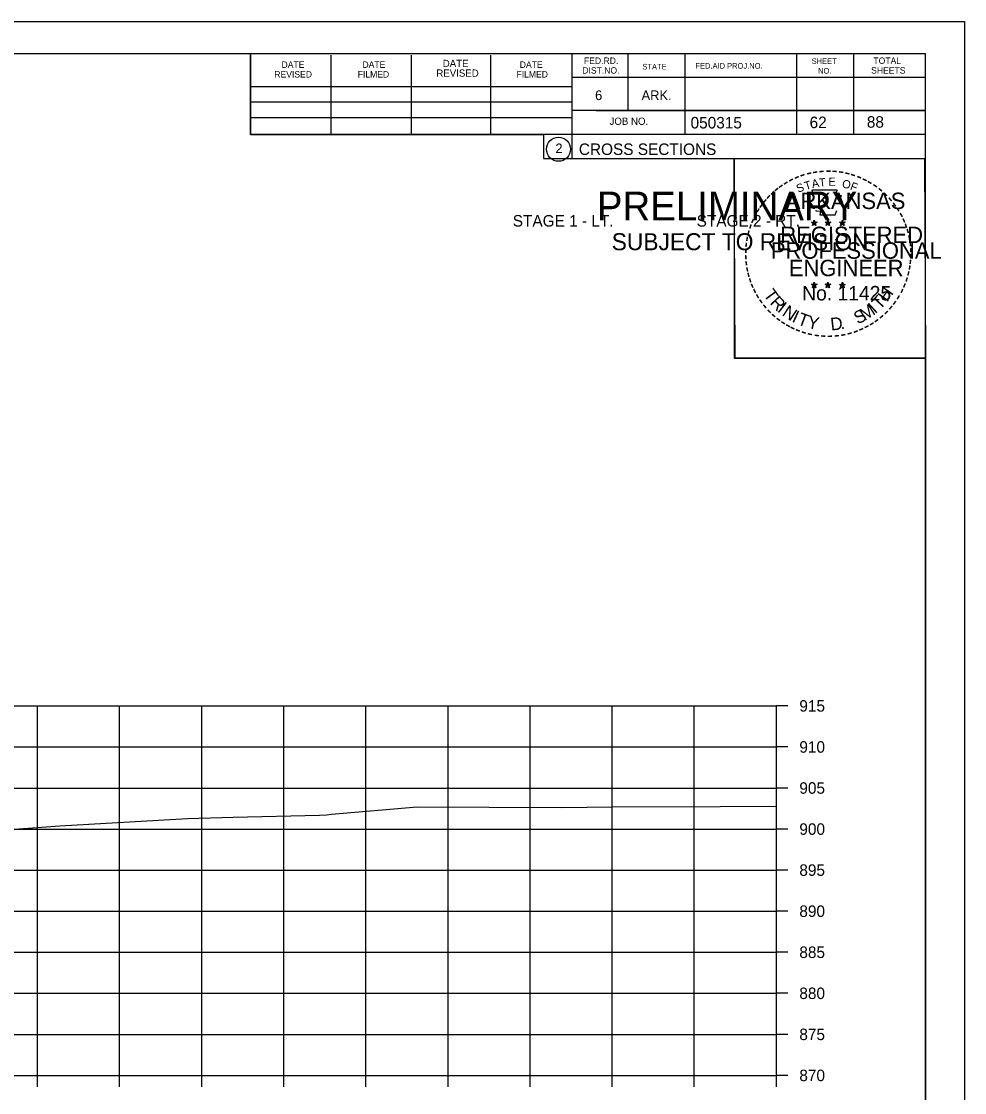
# Model space of a CAD drawing. Extents: x 1486524 to 1499135, y 326561 to 337924.
# Drawn here: x 1489030.9 to 1489145.8, y 330728.8 to 330859.3 of the extents above; entities that cross this region are included whole.
import ezdxf

# ---------------------------------------------------------------- set-up
doc = ezdxf.new("R2010")
doc.units = 0
for name, color, linetype in [('Default', 7, 'Continuous'), ('E_Const Align', 7, 'Continuous'), ('E_Const Align Station', 7, 'Continuous'), ('E_Ownership Information', 7, 'Continuous'), ('E_Property Line', 7, 'Continuous'), ('E_Quarter Calls', 7, 'Continuous'), ('E_Section Line', 7, 'Continuous'), ('E_Station Offset', 7, 'Continuous'), ('E_Tract Number', 7, 'Continuous'), ('S_SIXTEEN_SECTION', 7, 'Continuous')]:
    doc.layers.add(name, color=color, linetype=linetype)

msp = doc.modelspace()

# ---------------------------------------------------------------- linework, layer by layer
at = {"layer": 'E_Const Align'}
for p, q in [((1489122.89, 330730.91), (1489122.89, 330775.91)), ((1489124.29, 330775.91), (1489122.89, 330775.91)), ((1489124.29, 330770.91), (1489122.89, 330770.91)), ((1489124.29, 330765.91), (1489122.89, 330765.91)), ((1489124.29, 330760.91), (1489122.89, 330760.91)), ((1489124.29, 330755.91), (1489122.89, 330755.91)), ((1489124.29, 330750.91), (1489122.89, 330750.91)), ((1489124.29, 330745.91), (1489122.89, 330745.91)), ((1489124.29, 330740.91), (1489122.89, 330740.91)), ((1489124.29, 330735.91), (1489122.89, 330735.91)), ((1488842.89, 330730.91), (1489122.89, 330730.91)), ((1489032.89, 330729.51), (1489032.89, 330730.91)), ((1489042.89, 330729.51), (1489042.89, 330730.91)), ((1489052.89, 330729.51), (1489052.89, 330730.91)), ((1489062.89, 330729.51), (1489062.89, 330730.91)), ((1489072.89, 330729.51), (1489072.89, 330730.91)), ((1489082.89, 330729.51), (1489082.89, 330730.91)), ((1489092.89, 330729.51), (1489092.89, 330730.91)), ((1489102.89, 330729.51), (1489102.89, 330730.91)), ((1489112.89, 330729.51), (1489112.89, 330730.91)), ((1489122.89, 330729.51), (1489122.89, 330730.91)), ((1489124.29, 330730.91), (1489122.89, 330730.91))]:
    msp.add_line(p, q, dxfattribs=at)
at = {"layer": 'E_Ownership Information'}
for p, q in [((1488842.89, 330775.91), (1489122.89, 330775.91)), ((1489032.89, 330730.91), (1489032.89, 330775.91)), ((1489042.89, 330730.91), (1489042.89, 330775.91)), ((1489052.89, 330730.91), (1489052.89, 330775.91)), ((1489062.89, 330730.91), (1489062.89, 330775.91)), ((1489072.89, 330730.91), (1489072.89, 330775.91)), ((1489082.89, 330730.91), (1489082.89, 330775.91)), ((1489092.89, 330730.91), (1489092.89, 330775.91)), ((1489102.89, 330730.91), (1489102.89, 330775.91)), ((1489112.89, 330730.91), (1489112.89, 330775.91)), ((1489122.89, 330730.91), (1489122.89, 330775.91)), ((1488842.89, 330770.91), (1489122.89, 330770.91)), ((1488842.89, 330765.91), (1489122.89, 330765.91)), ((1488842.89, 330760.91), (1489122.89, 330760.91)), ((1488842.89, 330755.91), (1489122.89, 330755.91)), ((1488842.89, 330750.91), (1489122.89, 330750.91)), ((1488842.89, 330745.91), (1489122.89, 330745.91)), ((1488842.89, 330740.91), (1489122.89, 330740.91)), ((1488842.89, 330735.91), (1489122.89, 330735.91)), ((1488842.89, 330730.91), (1489122.89, 330730.91))]:
    msp.add_line(p, q, dxfattribs=at)
at = {"layer": 'E_Property Line'}
for p, q in [((1488824.89, 330855.37), (1489141.07, 330855.37)), ((1489058.81, 330845.49), (1489058.81, 330855.37)), ((1489068.67, 330845.49), (1489068.67, 330855.17)), ((1489078.43, 330845.49), (1489078.43, 330855.17)), ((1489088.11, 330845.49), (1489088.11, 330855.17)), ((1489097.97, 330855.37), (1489097.97, 330842.57)), ((1489104.81, 330855.37), (1489104.81, 330848.43)), ((1489111.75, 330855.37), (1489111.75, 330845.49)), ((1489125.33, 330855.37), (1489125.33, 330845.49)), ((1489132.27, 330855.37), (1489132.27, 330845.49)), ((1489141.07, 330649.91), (1489141.07, 330855.37)), ((1489141.07, 330852.43), (1489097.97, 330852.43)), ((1489141.07, 330852.45), (1489141.07, 330852.45)), ((1489058.81, 330851.35), (1489097.97, 330851.35)), ((1489058.81, 330849.49), (1489097.97, 330849.49)), ((1489141.07, 330848.43), (1489097.97, 330848.43)), ((1489100.93, 330848.43), (1489141.07, 330848.43)), ((1489058.81, 330845.49), (1489058.81, 330847.55)), ((1489058.81, 330847.55), (1489097.97, 330847.55)), ((1489141.07, 330845.49), (1489058.81, 330845.49)), ((1489097.97, 330842.57), (1489141.07, 330842.57))]:
    msp.add_line(p, q, dxfattribs=at)
msp.add_circle((1489096.35, 330843.7), 1.47, dxfattribs=at)
at = {"layer": 'E_Quarter Calls'}
for p, q in [((1488812.48, 330859.26), (1489145.82, 330859.26)), ((1489117.1, 330820.11), (1489117.1, 330820.11))]:
    msp.add_line(p, q, dxfattribs=at)
for points in [[(1488812.48, 330859.26), (1489145.82, 330859.26), (1489145.82, 330645.93), (1488812.48, 330645.93)], [(1489058.81, 330855.37), (1489058.81, 330845.49), (1489094.54, 330845.49), (1489094.54, 330842.57), (1489117.74, 330842.57), (1489117.74, 330818.24), (1489141.07, 330818.24), (1489141.07, 330649.91), (1488824.89, 330649.91), (1488824.89, 330855.37)], [(1489117.74, 330842.57), (1489140.94, 330842.57), (1489141.07, 330818.24), (1489117.86, 330818.24)]]:
    msp.add_lwpolyline(points, close=True, dxfattribs=at)
at = {"layer": 'E_Tract Number'}
msp.add_lwpolyline([(1489028.42, 330760.78), (1489035.62, 330761.29), (1489051.15, 330762.21), (1489056.71, 330762.36), (1489067.25, 330762.62), (1489068.1, 330762.66), (1489068.69, 330762.73), (1489079.15, 330763.61), (1489087.9, 330763.57), (1489096.77, 330763.55), (1489102.94, 330763.61), (1489116.06, 330763.67), (1489122.89, 330763.7)], dxfattribs=at)
at = {"layer": 'S_SIXTEEN_SECTION'}
for p, q in [((1489127.15, 330834.82), (1489127.5, 330834.71)), ((1489127.15, 330834.82), (1489127.4, 330834.78)), ((1489127.15, 330834.82), (1489127.39, 330834.7)), ((1489127.28, 330834.42), (1489127.5, 330834.71)), ((1489127.28, 330834.42), (1489127.41, 330834.66)), ((1489127.28, 330834.42), (1489127.5, 330834.63)), ((1489127.5, 330835.08), (1489127.46, 330834.83)), ((1489127.5, 330834.71), (1489127.5, 330835.08)), ((1489127.5, 330835.08), (1489127.55, 330834.83)), ((1489127.85, 330834.82), (1489127.5, 330834.71)), ((1489127.71, 330834.42), (1489127.5, 330834.71)), ((1489127.71, 330834.42), (1489127.5, 330834.63)), ((1489127.85, 330834.82), (1489127.56, 330834.78)), ((1489127.71, 330834.42), (1489127.58, 330834.71)), ((1489127.85, 330834.82), (1489127.64, 330834.72)), ((1489128.82, 330834.82), (1489129.17, 330834.71)), ((1489128.82, 330834.82), (1489129.07, 330834.78)), ((1489128.82, 330834.82), (1489129.06, 330834.7)), ((1489128.95, 330834.42), (1489129.17, 330834.71)), ((1489128.95, 330834.42), (1489129.08, 330834.66)), ((1489128.95, 330834.42), (1489129.17, 330834.63)), ((1489129.17, 330835.08), (1489129.13, 330834.83)), ((1489129.17, 330834.71), (1489129.17, 330835.08)), ((1489129.17, 330835.08), (1489129.22, 330834.83)), ((1489129.52, 330834.82), (1489129.17, 330834.71)), ((1489129.38, 330834.42), (1489129.17, 330834.71)), ((1489129.38, 330834.42), (1489129.17, 330834.63)), ((1489129.52, 330834.82), (1489129.23, 330834.78)), ((1489129.38, 330834.42), (1489129.25, 330834.71)), ((1489129.52, 330834.82), (1489129.31, 330834.72)), ((1489130.58, 330834.81), (1489130.93, 330834.7)), ((1489130.58, 330834.81), (1489130.84, 330834.77)), ((1489130.58, 330834.81), (1489130.82, 330834.69)), ((1489130.72, 330834.4), (1489130.93, 330834.7)), ((1489130.72, 330834.4), (1489130.84, 330834.65)), ((1489130.72, 330834.4), (1489130.93, 330834.62)), ((1489130.93, 330835.07), (1489130.89, 330834.81)), ((1489130.93, 330834.7), (1489130.93, 330835.07)), ((1489130.93, 330835.07), (1489130.98, 330834.82)), ((1489131.28, 330834.81), (1489130.93, 330834.7)), ((1489131.15, 330834.4), (1489130.93, 330834.7)), ((1489131.15, 330834.4), (1489130.93, 330834.62)), ((1489131.28, 330834.81), (1489130.99, 330834.76)), ((1489131.15, 330834.4), (1489131.01, 330834.7)), ((1489131.28, 330834.81), (1489131.08, 330834.71)), ((1489127.5, 330827.51), (1489127.45, 330827.25)), ((1489127.5, 330827.14), (1489127.5, 330827.51)), ((1489127.5, 330827.51), (1489127.54, 330827.26)), ((1489129.16, 330827.51), (1489129.12, 330827.25)), ((1489129.16, 330827.14), (1489129.16, 330827.51)), ((1489129.16, 330827.51), (1489129.21, 330827.26)), ((1489130.93, 330827.5), (1489130.89, 330827.24)), ((1489130.93, 330827.13), (1489130.93, 330827.5)), ((1489130.93, 330827.5), (1489130.98, 330827.25)), ((1489127.15, 330827.25), (1489127.5, 330827.14)), ((1489127.15, 330827.25), (1489127.4, 330827.21)), ((1489127.15, 330827.25), (1489127.38, 330827.13)), ((1489127.28, 330826.84), (1489127.5, 330827.14)), ((1489127.28, 330826.84), (1489127.41, 330827.09)), ((1489127.28, 330826.84), (1489127.49, 330827.06)), ((1489127.71, 330826.84), (1489127.49, 330827.06)), ((1489127.84, 330827.25), (1489127.5, 330827.14)), ((1489127.71, 330826.84), (1489127.5, 330827.14)), ((1489127.84, 330827.25), (1489127.56, 330827.2)), ((1489127.71, 330826.84), (1489127.57, 330827.13)), ((1489127.84, 330827.25), (1489127.64, 330827.15)), ((1489128.82, 330827.25), (1489129.16, 330827.14)), ((1489128.82, 330827.25), (1489129.07, 330827.21)), ((1489128.82, 330827.25), (1489129.05, 330827.13)), ((1489128.95, 330826.84), (1489129.16, 330827.14)), ((1489128.95, 330826.84), (1489129.07, 330827.09)), ((1489128.95, 330826.84), (1489129.16, 330827.06)), ((1489129.51, 330827.25), (1489129.16, 330827.14)), ((1489129.38, 330826.84), (1489129.16, 330827.14)), ((1489129.38, 330826.84), (1489129.16, 330827.06)), ((1489129.51, 330827.25), (1489129.23, 330827.2)), ((1489129.38, 330826.84), (1489129.24, 330827.13)), ((1489129.51, 330827.25), (1489129.31, 330827.15)), ((1489130.58, 330827.24), (1489130.93, 330827.13)), ((1489130.58, 330827.24), (1489130.84, 330827.2)), ((1489130.58, 330827.24), (1489130.82, 330827.12)), ((1489130.72, 330826.83), (1489130.93, 330827.13)), ((1489130.72, 330826.83), (1489130.84, 330827.08)), ((1489130.72, 330826.83), (1489130.93, 330827.05)), ((1489131.28, 330827.24), (1489130.93, 330827.13)), ((1489131.14, 330826.83), (1489130.93, 330827.13)), ((1489131.14, 330826.83), (1489130.93, 330827.05)), ((1489131.28, 330827.24), (1489130.99, 330827.19)), ((1489131.14, 330826.83), (1489131.01, 330827.12)), ((1489131.28, 330827.24), (1489131.07, 330827.14))]:
    msp.add_line(p, q, dxfattribs=at)
for points in [[(1489127.19, 330838.7), (1489127.46, 330837.88)], [(1489130.7, 330837.78), (1489130.84, 330838.06), (1489130.16, 330838.04), (1489130.31, 330838.7), (1489127.19, 330838.7)], [(1489127.68, 330836.28), (1489127.68, 330836.19), (1489128.25, 330836.17), (1489128.19, 330835.7), (1489130.06, 330835.7), (1489130.26, 330836.24)], [(1489127.5, 330835.08), (1489127.71, 330834.42), (1489127.15, 330834.82), (1489127.85, 330834.82), (1489127.28, 330834.42), (1489127.5, 330835.08)], [(1489129.17, 330835.08), (1489129.38, 330834.42), (1489128.82, 330834.82), (1489129.52, 330834.82), (1489128.95, 330834.42), (1489129.17, 330835.08)], [(1489130.93, 330835.07), (1489131.15, 330834.4), (1489130.58, 330834.81), (1489131.28, 330834.81), (1489130.72, 330834.4), (1489130.93, 330835.07)], [(1489127.5, 330827.51), (1489127.71, 330826.84), (1489127.15, 330827.25), (1489127.84, 330827.25), (1489127.28, 330826.84), (1489127.5, 330827.51)], [(1489129.16, 330827.51), (1489129.38, 330826.84), (1489128.82, 330827.25), (1489129.51, 330827.25), (1489128.95, 330826.84), (1489129.16, 330827.51)], [(1489130.93, 330827.5), (1489131.14, 330826.83), (1489130.58, 330827.24), (1489131.28, 330827.24), (1489130.72, 330826.83), (1489130.93, 330827.5)]]:
    msp.add_lwpolyline(points, dxfattribs=at)
for centre, radius in [((1489127.5, 330834.71), 0.172), ((1489127.5, 330834.71), 0.145), ((1489127.5, 330834.71), 0.116), ((1489127.5, 330834.71), 0.0991), ((1489127.5, 330834.71), 0.0747), ((1489127.5, 330834.71), 0.0495), ((1489127.5, 330834.71), 0.0296), ((1489129.17, 330834.71), 0.172), ((1489129.17, 330834.71), 0.145), ((1489129.17, 330834.71), 0.116), ((1489129.17, 330834.71), 0.0991), ((1489129.17, 330834.71), 0.0747), ((1489129.17, 330834.71), 0.0495), ((1489129.17, 330834.71), 0.0296), ((1489130.93, 330834.7), 0.172), ((1489130.93, 330834.7), 0.145), ((1489130.93, 330834.7), 0.116), ((1489130.93, 330834.7), 0.0991), ((1489130.93, 330834.7), 0.0747), ((1489130.93, 330834.7), 0.0495), ((1489130.93, 330834.7), 0.0296), ((1489127.49, 330827.14), 0.172), ((1489127.49, 330827.14), 0.145), ((1489127.49, 330827.14), 0.116), ((1489127.49, 330827.14), 0.0991), ((1489127.49, 330827.14), 0.0747), ((1489127.49, 330827.14), 0.0495), ((1489127.49, 330827.14), 0.0296), ((1489129.16, 330827.14), 0.172), ((1489129.16, 330827.14), 0.145), ((1489129.16, 330827.14), 0.116), ((1489129.16, 330827.14), 0.0991), ((1489129.16, 330827.14), 0.0747), ((1489129.16, 330827.14), 0.0495), ((1489129.16, 330827.14), 0.0296), ((1489130.93, 330827.13), 0.172), ((1489130.93, 330827.13), 0.145), ((1489130.93, 330827.13), 0.116), ((1489130.93, 330827.13), 0.0991), ((1489130.93, 330827.13), 0.0747), ((1489130.93, 330827.13), 0.0495), ((1489130.93, 330827.13), 0.0296)]:
    msp.add_circle(centre, radius, dxfattribs=at)

# ---------------------------------------------------------------- texts
at = {"layer": 'Default'}
for s, p in [('STAGE 1 - LT.', (1489090.78, 330834.28)), ('STAGE 2 - RT.', (1489113.18, 330834.28))]:
    msp.add_text(s, height=1.4, dxfattribs=at).set_placement(p)
at = {"layer": 'E_Const Align Station'}
for s, p in [('915', (1489125.69, 330775.21)), ('910', (1489125.69, 330770.21)), ('905', (1489125.69, 330765.21)), ('900', (1489125.69, 330760.21)), ('895', (1489125.69, 330755.21)), ('890', (1489125.69, 330750.21)), ('885', (1489125.69, 330745.21)), ('880', (1489125.69, 330740.21)), ('875', (1489125.69, 330735.21)), ('870', (1489125.69, 330730.21))]:
    msp.add_text(s, height=1.4, dxfattribs=at).set_placement(p)
at = {"layer": 'E_Property Line'}
for s, height, p in [('FED.RD.', 0.782, (1489099.45, 330854.09)), ('TOTAL', 0.782, (1489134.71, 330854.09)), ('DATE', 0.782, (1489062.61, 330853.61)), ('DATE', 0.782, (1489072.47, 330853.61)), ('DATE', 0.879, (1489082.25, 330853.71)), ('DATE', 0.782, (1489091.63, 330853.61)), ('DIST.NO.', 0.782, (1489099.25, 330852.91)), ('STATE', 0.684, (1489106.57, 330853.41)), ('FED.AID PROJ.NO.', 0.684, (1489113.03, 330853.51)), ('SHEET', 0.684, (1489127.19, 330854.09)), ('NO.', 0.684, (1489127.97, 330852.91)), ('SHEETS', 0.782, (1489134.43, 330852.91)), ('REVISED', 0.782, (1489061.73, 330852.43)), ('FILMED', 0.782, (1489071.89, 330852.43)), ('REVISED', 0.879, (1489081.47, 330852.53)), ('FILMED', 0.782, (1489091.23, 330852.43)), ('6', 1.17, (1489100.81, 330849.69)), ('ARK.', 1.172, (1489106.47, 330849.69)), ('JOB NO.', 0.879, (1489102.57, 330846.67)), ('050315', 1.4, (1489112.44, 330846.23)), ('2', 1.17, (1489095.97, 330843.22)), ('CROSS SECTIONS', 1.4, (1489098.83, 330843))]:
    msp.add_text(s, height=height, rotation=360, dxfattribs=at).set_placement(p)
at = {"layer": 'E_Section Line'}
for s, height, p in [('PRELIMINARY', 3.5, (1489101.02, 330835.03)), ('DWB', 0.01, (1489101.76, 330836.88)), ('SUBJECT TO REVISION', 2.0751, (1489102.83, 330831.4))]:
    msp.add_text(s, height=height, rotation=360, dxfattribs=at).set_placement(p)
at = {"layer": 'E_Station Offset'}
for s, p in [('62', (1489126.94, 330846.27)), ('88', (1489133.91, 330846.32))]:
    msp.add_text(s, height=1.4, dxfattribs=at).set_placement(p)
at = {"layer": 'S_SIXTEEN_SECTION'}
for s, height, rotation, p in [('-', 1.6, 19.1761, (1489125.94, 330839.83)), ('-', 1.6, 13.6301, (1489126.69, 330840.07)), ('-', 1.6, 10.2193, (1489127.37, 330840.23)), ('-', 1.6, 5.8968, (1489128.1, 330840.34)), ('-', 1.6, 0.1862, (1489128.87, 330840.41)), ('-', 1.6, 357.743, (1489129.59, 330840.4)), ('-', 1.6, 352.1617, (1489130.34, 330840.35)), ('-', 1.6, 347.2049, (1489131.05, 330840.23)), ('-', 1.6, 342.3362, (1489131.69, 330840.08)), ('-', 1.6, 337.8551, (1489132.42, 330839.85)), ('-', 1.6, 36.2317, (1489123.5, 330838.48)), ('-', 1.6, 34.0636, (1489124.08, 330838.87)), ('-', 1.6, 28.7918, (1489124.67, 330839.24)), ('-', 1.6, 24.3072, (1489125.31, 330839.56)), ('S', 1, 21.594, (1489125.55, 330838.38)), ('T', 1, 16.4036, (1489126.46, 330838.71)), ('A', 1, 11.2132, (1489127.29, 330838.96)), ('T', 1, 6.0228, (1489128.14, 330839.13)), ('E', 1, 0.8323, (1489129.24, 330839.24)), ('O', 1, 350.4515, (1489130.84, 330839.03)), ('F', 1, 340.0707, (1489131.8, 330838.8)), ('-', 1.6, 334.1211, (1489133.06, 330839.58)), ('-', 1.6, 329.6409, (1489133.63, 330839.3)), ('-', 1.6, 325.8627, (1489134.28, 330838.94)), ('-', 1.6, 48.423, (1489122.14, 330837.21)), ('-', 1.6, 42.9622, (1489122.59, 330837.68)), ('-', 1.6, 38.9507, (1489123.02, 330838.1)), ('ARKANSAS', 2, 360, (1489124.04, 330836.41)), ('-', 1.6, 320.5297, (1489134.89, 330838.51)), ('-', 1.6, 315.5786, (1489135.49, 330838.02)), ('-', 1.6, 54.2325, (1489121.32, 330836.15)), ('-', 1.6, 50.6142, (1489121.74, 330836.72)), ('-', 1.6, 309.8797, (1489136.06, 330837.47)), ('-', 1.6, 306.6522, (1489136.58, 330836.87)), ('-', 1.4, 303.6753, (1489137.07, 330836.3)), ('-', 1.6, 62.8713, (1489120.69, 330835.01)), ('-', 1.6, 58.0706, (1489121, 330835.63)), ('-', 1.6, 299.6684, (1489137.39, 330835.7)), ('-', 1.6, 294.6628, (1489137.71, 330835.09)), ('-', 1.6, 72.3945, (1489120.21, 330833.77)), ('-', 1.6, 67.7743, (1489120.43, 330834.4)), ('REGISTERED', 2, 360, (1489123.37, 330832.27)), ('DWB', 0.01, 360, (1489127.49, 330834.71)), ('DWB', 0.01, 360, (1489129.16, 330834.71)), ('DWB', 0.01, 360, (1489130.92, 330834.7)), ('-', 1.6, 290.5728, (1489137.97, 330834.51)), ('-', 1.6, 285.1233, (1489138.2, 330833.93)), ('-', 1.6, 81.2013, (1489119.88, 330832.34)), ('-', 1.6, 75.461, (1489120.01, 330833.06)), ('-', 1.6, 280.5493, (1489138.4, 330833.19)), ('-', 1.6, 89.0622, (1489119.78, 330830.95)), ('-', 1.6, 85.1863, (1489119.8, 330831.65)), ('PROFESSIONAL', 2, 360, (1489122.22, 330830.36)), ('-', 1.6, 276.5962, (1489138.56, 330832.42)), ('-', 1.6, 274.3301, (1489138.62, 330831.7)), ('-', 1.6, 94.1959, (1489119.81, 330830.23)), ('-', 1.6, 98.9479, (1489119.89, 330829.56)), ('ENGINEER', 2, 360, (1489124.41, 330828.24)), ('-', 1.6, 263.5172, (1489138.64, 330830.4)), ('-', 1.6, 269.9407, (1489138.66, 330831.06)), ('-', 1.6, 101.7149, (1489120.02, 330828.83)), ('-', 1.6, 255.7626, (1489138.46, 330829.07)), ('-', 1.6, 260.9953, (1489138.57, 330829.74)), ('-', 1.6, 105.4578, (1489120.18, 330828.23)), ('-', 1.6, 109.0874, (1489120.4, 330827.6)), ('-', 1.6, 252.8681, (1489138.28, 330828.35)), ('-', 1.6, 114.0643, (1489120.65, 330827)), ('-', 1.6, 115.7289, (1489120.96, 330826.39)), ('T', 1.54, 306.0406, (1489121.25, 330825.98)), ('No. 11425', 1.757, 360, (1489126.03, 330825.29)), ('DWB', 0.01, 360, (1489127.48, 330827.14)), ('DWB', 0.01, 360, (1489129.15, 330827.14)), ('DWB', 0.01, 360, (1489130.92, 330827.13)), ('H', 1.54, 54.6088, (1489136.38, 330825.01)), ('-', 1.6, 244.6197, (1489137.79, 330827.04)), ('-', 1.6, 247.8887, (1489138.05, 330827.67)), ('-', 1.6, 120.4471, (1489121.31, 330825.8)), ('-', 1.6, 125.8934, (1489121.72, 330825.24)), ('R', 1.54, 314.005, (1489122.02, 330824.93)), ('I', 1.54, 321.9694, (1489122.92, 330824)), ('M', 1.54, 32.6563, (1489133.64, 330822.75)), ('I', 1.54, 42.1136, (1489134.92, 330823.59)), ('T', 1.54, 46.6444, (1489135.49, 330824.07)), ('-', 1.6, 233.8452, (1489136.99, 330825.64)), ('-', 1.6, 239.0712, (1489137.4, 330826.29)), ('-', 1.6, 130.7181, (1489122.18, 330824.69)), ('-', 1.6, 134.2238, (1489122.7, 330824.14)), ('-', 1.6, 138.9338, (1489123.22, 330823.68)), ('N', 1.54, 326.5002, (1489123.49, 330823.53)), ('I', 1.54, 335.3603, (1489124.69, 330822.74)), ('T', 1.54, 339.8912, (1489125.35, 330822.41)), ('S', 1.54, 26.9312, (1489132.8, 330822.34)), ('-', 1.6, 221.0851, (1489135.56, 330824)), ('-', 1.6, 225.7653, (1489136.09, 330824.51)), ('-', 1.6, 231.2538, (1489136.56, 330825.07)), ('-', 1.6, 144.6463, (1489123.78, 330823.27)), ('-', 1.6, 148.0898, (1489124.34, 330822.9)), ('-', 1.6, 151.5704, (1489124.92, 330822.58)), ('Y', 1.54, 347.8556, (1489126.57, 330821.97)), ('D', 1.54, 6.3969, (1489129.56, 330821.61)), ('-', 1.6, 207.3568, (1489133.92, 330822.8)), ('-', 1.6, 212.2491, (1489134.48, 330823.14)), ('-', 1.6, 215.7363, (1489135.01, 330823.53)), ('-', 1.6, 154.6002, (1489125.44, 330822.33)), ('-', 1.6, 158.5612, (1489126.06, 330822.08)), ('-', 1.6, 162.7983, (1489126.75, 330821.86)), ('-', 1.6, 167.5555, (1489127.46, 330821.7)), ('-', 1.6, 173.1155, (1489128.24, 330821.59)), ('-', 1.6, 176.5183, (1489128.98, 330821.54)), ('-', 1.6, 181.5918, (1489129.73, 330821.55)), ('-', 1.6, 185.8167, (1489130.54, 330821.63)), ('-', 1.6, 191.2858, (1489131.27, 330821.76)), ('.', 1.54, 13.7642, (1489130.75, 330821.74)), ('-', 1.6, 195.4743, (1489132, 330821.96)), ('-', 1.6, 200.7184, (1489132.68, 330822.2)), ('-', 1.6, 204.2516, (1489133.3, 330822.48))]:
    msp.add_text(s, height=height, rotation=rotation, dxfattribs=at).set_placement(p)

doc.saveas('drawing.dxf')
